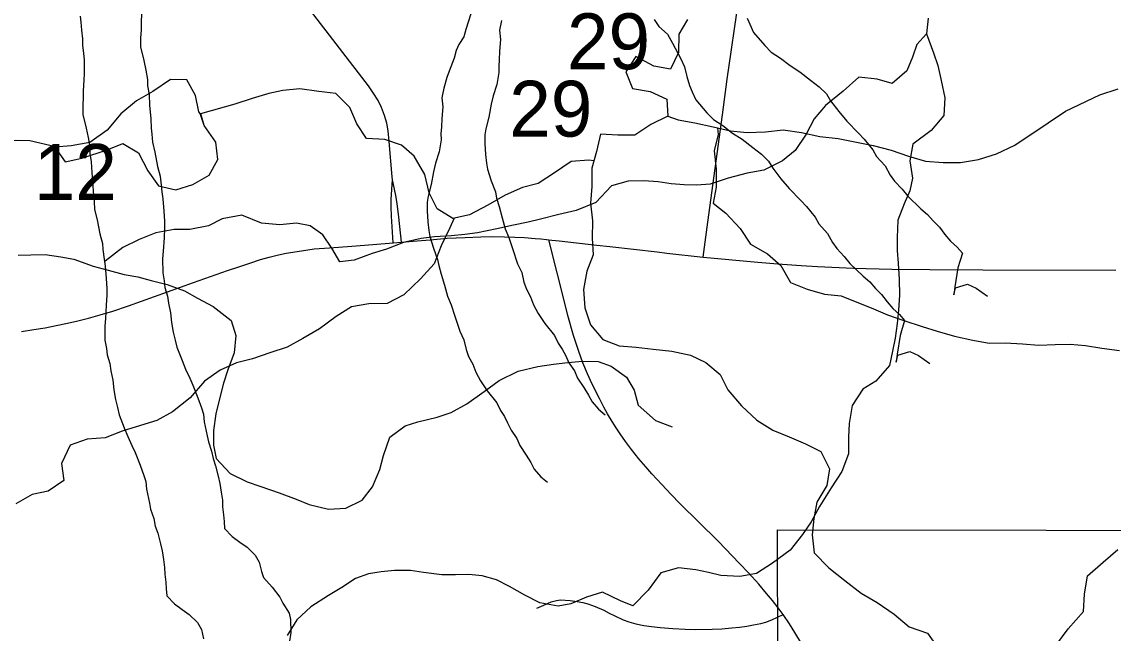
# Model space of a CAD drawing. Extents: x -21.1 to 50.3, y 0 to 22.1.
# Drawn here: x 3.891 to 4.709, y 20.075 to 20.533 of the extents above; entities that cross this region are included whole.
import ezdxf

# ---------------------------------------------------------------- set-up
doc = ezdxf.new("R2010")
doc.units = 0
for name, color, linetype in [('GM_X_Minor_Lake', 7, 'Continuous'), ('GM_X_Minor_River', 7, 'Continuous'), ('GM_X_Section', 7, 'Continuous'), ('GM_X_Section_Text', 7, 'Continuous'), ('GM_X_State_Route', 7, 'Continuous'), ('GM_X_Township_Road', 7, 'Continuous')]:
    doc.layers.add(name, color=color, linetype=linetype)

msp = doc.modelspace()

# ---------------------------------------------------------------- linework, layer by layer
at = {"layer": 'GM_X_Minor_Lake'}
for points in [[(4.02474, 20.46486), (4.02392, 20.46603), (4.02124, 20.4782), (4.01476, 20.48998), (4.00258, 20.49034), (3.98928, 20.4812), (3.97711, 20.47434), (3.96533, 20.46444), (3.95507, 20.45225), (3.94215, 20.44311), (3.92807, 20.44043), (3.9159, 20.43965), (3.92353, 20.42863)], [(3.92353, 20.42863), (3.93608, 20.43131), (3.95509, 20.43742), (3.96688, 20.44238), (3.97869, 20.43517), (3.98556, 20.42186), (3.99357, 20.41046), (4.00651, 20.40744), (4.01944, 20.41164), (4.0316, 20.4185), (4.03805, 20.4303), (4.03651, 20.44323), (4.02775, 20.45576), (4.02474, 20.46486)], [(3.92353, 20.42863), (3.93608, 20.43131), (3.95509, 20.43742), (3.96688, 20.44238), (3.97869, 20.43517), (3.98556, 20.42186), (3.99357, 20.41046), (4.00651, 20.40744), (4.01944, 20.41164), (4.0316, 20.4185), (4.03805, 20.4303), (4.03651, 20.44323), (4.02775, 20.45576), (4.0252, 20.4644)]]:
    msp.add_lwpolyline(points, dxfattribs=at)
at = {"layer": 'GM_X_Minor_River'}
for points in [[(3.93498, 20.53781), (3.93538, 20.53325)], [(3.98082, 20.54047), (3.98048, 20.53211), (3.98051, 20.52717), (3.98016, 20.52147), (3.9802, 20.51463), (3.98254, 20.50439), (3.98411, 20.49718), (3.98529, 20.49035), (3.98531, 20.48541), (3.98649, 20.47896), (3.98692, 20.47098), (3.98774, 20.46073), (3.98815, 20.45389), (3.98856, 20.44934), (3.98898, 20.44326), (3.99092, 20.43567), (3.99289, 20.42505), (3.99483, 20.41784), (3.99523, 20.41328), (3.99604, 20.40607), (3.99683, 20.40076), (3.99764, 20.39164), (3.99806, 20.38405), (3.99809, 20.37911), (3.99775, 20.37151), (3.99705, 20.36163), (3.9967, 20.35593), (3.99676, 20.34529), (3.99793, 20.33922), (3.99834, 20.33428), (4.00028, 20.32783), (4.00107, 20.32252), (4.00264, 20.31531), (4.00344, 20.3081), (4.00462, 20.30089), (4.00618, 20.29481), (4.00735, 20.2895), (4.01121, 20.27965), (4.01391, 20.27321), (4.017, 20.26638), (4.01931, 20.26108), (4.02317, 20.2516), (4.02587, 20.24402), (4.02742, 20.23947), (4.02784, 20.23377), (4.03018, 20.22315), (4.03097, 20.21859), (4.03329, 20.21177), (4.03446, 20.20608), (4.0364, 20.20077), (4.03834, 20.1928), (4.03952, 20.18749), (4.04069, 20.18104), (4.04149, 20.17496), (4.04152, 20.17003), (4.04231, 20.16395), (4.04272, 20.15902), (4.04313, 20.1537), (4.04887, 20.14765), (4.05461, 20.14351), (4.05996, 20.13974), (4.06608, 20.13369), (4.06916, 20.12839), (4.07072, 20.12156), (4.07226, 20.11701), (4.07878, 20.10983), (4.08453, 20.10226), (4.08684, 20.09772), (4.09145, 20.09015), (4.09262, 20.08559), (4.09267, 20.07572), (4.09157, 20.06773)], [(4.22769, 20.53944), (4.22395, 20.52764), (4.22246, 20.52231), (4.21868, 20.51659), (4.21681, 20.51202), (4.21531, 20.50632), (4.21156, 20.49642), (4.20968, 20.49185), (4.20745, 20.48386), (4.20596, 20.47663), (4.20677, 20.4698), (4.20605, 20.46106), (4.20571, 20.4546), (4.20535, 20.44966), (4.20538, 20.4451), (4.20391, 20.43597), (4.20129, 20.4276), (4.1998, 20.42113), (4.19795, 20.41162), (4.19572, 20.40287), (4.19498, 20.39831), (4.19502, 20.39185), (4.19545, 20.3835), (4.19624, 20.37704), (4.19703, 20.37249), (4.19974, 20.36377), (4.20284, 20.35543), (4.20363, 20.35087), (4.20556, 20.34442), (4.20789, 20.33608), (4.21023, 20.32773), (4.21292, 20.32129), (4.21564, 20.31295), (4.21951, 20.30157), (4.22259, 20.29513), (4.22415, 20.28792), (4.22608, 20.28261), (4.22916, 20.27693), (4.23148, 20.27087), (4.23494, 20.26443), (4.23993, 20.25686), (4.24722, 20.24778), (4.24991, 20.2421), (4.25298, 20.23756), (4.25529, 20.23301), (4.25799, 20.22733), (4.26221, 20.22127), (4.26452, 20.21597), (4.26913, 20.20877), (4.27259, 20.20309), (4.27528, 20.19817), (4.28026, 20.1925), (4.28523, 20.18835)], [(4.57054, 20.53612), (4.5694, 20.52437), (4.5747, 20.51034), (4.57773, 20.50085), (4.58038, 20.48948), (4.58302, 20.47658), (4.58225, 20.46331), (4.57277, 20.45193), (4.55912, 20.44169), (4.55684, 20.42917), (4.55873, 20.41628), (4.55683, 20.4068), (4.55265, 20.39694), (4.54772, 20.3848), (4.54733, 20.37191), (4.54733, 20.36204), (4.54808, 20.35256), (4.54883, 20.34043), (4.5492, 20.32867), (4.54844, 20.31729), (4.54729, 20.30743), (4.54577, 20.29643), (4.54387, 20.28657), (4.54159, 20.27595), (4.53135, 20.2642), (4.52149, 20.25813), (4.51352, 20.24599), (4.51124, 20.23234), (4.51086, 20.2221), (4.51085, 20.20958), (4.50591, 20.19631), (4.49794, 20.18417), (4.48922, 20.17014), (4.48277, 20.15876), (4.47632, 20.14928), (4.46722, 20.13752), (4.45394, 20.12766), (4.44181, 20.12007), (4.4293, 20.11779), (4.41527, 20.11855), (4.40579, 20.12083), (4.39632, 20.12272), (4.38343, 20.12424), (4.37016, 20.12044), (4.36068, 20.10755), (4.3493, 20.09579), (4.33982, 20.09958), (4.32656, 20.10603), (4.31443, 20.10223), (4.30267, 20.0973), (4.29319, 20.0954), (4.27955, 20.09806), (4.26818, 20.10374), (4.25681, 20.11019), (4.24696, 20.11512), (4.23634, 20.11815), (4.22611, 20.11929)], [(4.43496, 20.53616), (4.43689, 20.53161), (4.43959, 20.52555), (4.44802, 20.51572), (4.453, 20.5108), (4.45987, 20.50628), (4.46714, 20.50063), (4.47439, 20.49611), (4.48242, 20.4897), (4.48892, 20.48479), (4.49428, 20.4795), (4.49736, 20.4742), (4.50349, 20.46626), (4.50962, 20.45907), (4.51843, 20.45001), (4.52264, 20.44547), (4.52915, 20.43753), (4.53185, 20.4326), (4.53836, 20.42542), (4.5422, 20.41861), (4.54527, 20.41406), (4.55102, 20.40802), (4.55523, 20.40272), (4.56518, 20.39328), (4.57016, 20.38913), (4.57437, 20.38421), (4.57896, 20.37968), (4.58318, 20.37401), (4.5874, 20.36909), (4.59237, 20.36456), (4.5962, 20.36002), (4.59284, 20.34898), (4.59064, 20.33492), (4.58991, 20.32884), (4.59102, 20.33416), (4.60014, 20.33687), (4.60663, 20.33387), (4.61504, 20.32784)], [(3.93538, 20.53325), (3.9358, 20.52718), (3.9366, 20.52072), (3.93662, 20.51578), (3.93742, 20.51009), (3.93783, 20.50477), (3.93788, 20.49451), (3.93753, 20.48996), (3.93719, 20.48159), (3.93722, 20.47666), (3.93688, 20.47096), (3.93691, 20.46412), (3.93925, 20.45387), (3.94082, 20.44666), (3.942, 20.43983), (3.94202, 20.43489), (3.9432, 20.42844), (3.94363, 20.42047), (3.94445, 20.41021), (3.94487, 20.40338), (3.94527, 20.39882), (3.94569, 20.39275), (3.94763, 20.38516), (3.9496, 20.37453), (3.95154, 20.36732), (3.95195, 20.36277), (3.95275, 20.35556), (3.95354, 20.35024), (3.95435, 20.34113), (3.95477, 20.33353), (3.9548, 20.32859), (3.95446, 20.32099), (3.95376, 20.31111), (3.95341, 20.30541), (3.95347, 20.29477), (3.95464, 20.2887), (3.95505, 20.28377), (3.95699, 20.27732), (3.95778, 20.272), (3.95935, 20.26479), (3.96015, 20.25758), (3.96133, 20.25037), (3.96289, 20.2443), (3.96406, 20.23899), (3.96792, 20.22913), (3.97062, 20.22269), (3.97371, 20.21587), (3.97602, 20.21056), (3.97988, 20.20108), (3.98259, 20.1935), (3.98413, 20.18895), (3.98455, 20.18326), (3.98689, 20.17263), (3.98768, 20.16808), (3.99, 20.16125), (3.99117, 20.15556), (3.99311, 20.15025), (3.99505, 20.14229), (3.99623, 20.13697), (3.99741, 20.13052), (3.9982, 20.12445), (3.99823, 20.11951), (3.99902, 20.11343), (3.99943, 20.1085), (3.99984, 20.10318), (4.00559, 20.09714), (4.01132, 20.09299), (4.01667, 20.08922), (4.02279, 20.08318), (4.02587, 20.07787), (4.02743, 20.07105)], [(4.25074, 20.53437), (4.24925, 20.52715), (4.25005, 20.52031), (4.24934, 20.51157), (4.249, 20.50511), (4.24864, 20.50017), (4.24867, 20.49561), (4.2472, 20.48649), (4.24458, 20.47811), (4.24309, 20.47165), (4.24124, 20.46214), (4.23901, 20.45339), (4.23827, 20.44883), (4.23831, 20.44237), (4.23874, 20.43402), (4.23953, 20.42756), (4.24032, 20.42301), (4.24303, 20.41428), (4.24613, 20.40594), (4.24691, 20.40139), (4.24885, 20.39494), (4.25118, 20.38659), (4.25351, 20.37825), (4.25621, 20.37181), (4.25893, 20.36346), (4.26279, 20.35209), (4.26588, 20.34565), (4.26744, 20.33844), (4.26937, 20.33313), (4.27245, 20.32745), (4.27477, 20.32138), (4.27823, 20.31495), (4.28322, 20.30738), (4.29051, 20.2983), (4.2932, 20.29261), (4.29627, 20.28807), (4.29858, 20.28353), (4.30128, 20.27784), (4.3055, 20.27179), (4.30781, 20.26648), (4.31242, 20.25929), (4.31588, 20.25361), (4.31857, 20.24869), (4.32355, 20.24302), (4.32852, 20.23887)], [(4.39025, 20.53532), (4.38379, 20.52428), (4.38344, 20.51059), (4.37736, 20.49804), (4.36481, 20.5003), (4.35148, 20.50751), (4.34388, 20.49609), (4.34885, 20.48355), (4.36217, 20.48128), (4.37473, 20.47559), (4.37551, 20.46266), (4.36259, 20.45656), (4.3508, 20.44856), (4.33786, 20.44854), (4.32493, 20.44929), (4.3219, 20.43635), (4.31849, 20.4238), (4.31851, 20.41011), (4.31739, 20.39756), (4.31893, 20.38425), (4.31857, 20.37132), (4.31935, 20.35877), (4.3148, 20.34659), (4.31216, 20.33289), (4.31332, 20.3192), (4.31752, 20.30628), (4.32667, 20.29526), (4.33885, 20.29071), (4.35179, 20.28959), (4.36435, 20.28808), (4.37843, 20.28658), (4.39252, 20.28355), (4.40394, 20.27824), (4.41461, 20.26913), (4.42033, 20.25773), (4.43062, 20.24557), (4.44205, 20.23493), (4.45424, 20.22734), (4.46642, 20.22241), (4.47861, 20.2171), (4.49003, 20.21141), (4.49652, 20.19849), (4.49463, 20.18594), (4.48704, 20.17338), (4.48478, 20.1612), (4.48365, 20.14903), (4.48519, 20.13534), (4.49624, 20.12433), (4.50805, 20.11483), (4.52024, 20.10534), (4.53243, 20.09813), (4.545, 20.0894), (4.55643, 20.0799), (4.57013, 20.07536), (4.57738, 20.0651)], [(4.36513, 20.53526), (4.36859, 20.52996), (4.37509, 20.5243), (4.37893, 20.51748), (4.38509, 20.50574), (4.38779, 20.49968), (4.38973, 20.49247), (4.39167, 20.48564), (4.3936, 20.48109), (4.3963, 20.47503), (4.40473, 20.4652), (4.40971, 20.46029), (4.41658, 20.45577), (4.42385, 20.45011), (4.4311, 20.44559), (4.43913, 20.43918), (4.44563, 20.43428), (4.45099, 20.42899), (4.45407, 20.42369), (4.4602, 20.41574), (4.46633, 20.40856), (4.47514, 20.39949), (4.47935, 20.39495), (4.48587, 20.38701), (4.48856, 20.38209), (4.49507, 20.37491), (4.49892, 20.36809), (4.50199, 20.36355), (4.50773, 20.3575), (4.51195, 20.35221), (4.52189, 20.34276), (4.52687, 20.33861), (4.53108, 20.3337), (4.53567, 20.32917), (4.53989, 20.32349), (4.54411, 20.31857), (4.54908, 20.31404), (4.55292, 20.30951), (4.54955, 20.29847), (4.54735, 20.2844), (4.54662, 20.27832), (4.54773, 20.28365), (4.55685, 20.28635), (4.56334, 20.28335), (4.57175, 20.27732)], [(4.5694, 20.52437), (4.56219, 20.5164), (4.55878, 20.50692), (4.5546, 20.49668), (4.5436, 20.4872), (4.53223, 20.49061), (4.51859, 20.49213), (4.50683, 20.48151), (4.49355, 20.47089), (4.48521, 20.46065), (4.47914, 20.44927), (4.47079, 20.43713), (4.46131, 20.42917), (4.44728, 20.42234), (4.43477, 20.42006), (4.42074, 20.41627), (4.40709, 20.41172), (4.39724, 20.41096), (4.38776, 20.41133), (4.3779, 20.41209), (4.36805, 20.41361), (4.35743, 20.41437), (4.34568, 20.41398), (4.33317, 20.41057), (4.32141, 20.39805), (4.30662, 20.39198), (4.29373, 20.38895), (4.28008, 20.38553), (4.27061, 20.38326), (4.25961, 20.38098), (4.2471, 20.37832), (4.2327, 20.37529), (4.22322, 20.37415), (4.21298, 20.37301), (4.20047, 20.37225), (4.19061, 20.37111), (4.17735, 20.36808), (4.16445, 20.36315), (4.15384, 20.35973), (4.14019, 20.3548), (4.12958, 20.35366), (4.12351, 20.3639), (4.1167, 20.37376), (4.10722, 20.38059), (4.09699, 20.38248), (4.08448, 20.38134), (4.07083, 20.38248), (4.05605, 20.38854), (4.04127, 20.38589), (4.03103, 20.38058), (4.017, 20.37792), (4.00525, 20.37792), (3.9916, 20.37526), (3.97909, 20.37033), (3.96696, 20.36426), (3.95368, 20.35402)], [(4.31999, 20.4293), (4.3162, 20.42988), (4.30289, 20.42872), (4.29034, 20.42034), (4.27818, 20.41234), (4.26639, 20.40928), (4.25346, 20.40356), (4.24053, 20.39594), (4.22684, 20.3887), (4.21429, 20.38602), (4.20249, 20.39323), (4.19638, 20.40539), (4.19332, 20.41908), (4.18531, 20.43276), (4.17578, 20.44112), (4.16322, 20.44528), (4.14952, 20.44603), (4.14227, 20.45705), (4.13693, 20.46921), (4.12664, 20.47985), (4.1137, 20.48135), (4.09962, 20.48324), (4.08668, 20.48208), (4.07641, 20.47979), (4.06386, 20.47597), (4.05093, 20.47177), (4.02497, 20.46463)], [(4.37551, 20.46266), (4.38313, 20.46001), (4.39569, 20.45775), (4.40939, 20.45472), (4.42233, 20.45169), (4.43489, 20.45057), (4.44859, 20.45096), (4.4619, 20.4525), (4.4756, 20.45062), (4.48931, 20.44759), (4.50301, 20.44609), (4.51557, 20.44344), (4.52927, 20.4408), (4.54297, 20.43739), (4.55592, 20.43284), (4.56848, 20.42905), (4.5818, 20.42793), (4.59473, 20.42795), (4.60843, 20.43024), (4.62174, 20.43444), (4.63543, 20.44093), (4.66052, 20.45769), (4.67344, 20.46646), (4.6993, 20.47866), (4.71299, 20.48324)], [(4.41253, 20.45398), (4.4132, 20.44902), (4.41018, 20.43684), (4.41172, 20.42315), (4.41174, 20.40946), (4.40947, 20.39767), (4.419, 20.39007), (4.42967, 20.37868), (4.43729, 20.3669), (4.45024, 20.35969), (4.46015, 20.35095), (4.4674, 20.33803), (4.47996, 20.3331), (4.4929, 20.32932), (4.50546, 20.32819), (4.5184, 20.32288), (4.52792, 20.31909), (4.54011, 20.31378), (4.55229, 20.30961), (4.566, 20.30507), (4.57741, 20.30166), (4.59036, 20.29787), (4.60406, 20.29485), (4.61624, 20.29258), (4.62841, 20.29297), (4.64135, 20.29223), (4.65353, 20.2911), (4.66571, 20.2915), (4.67712, 20.29189), (4.68854, 20.29077), (4.70071, 20.28888), (4.71404, 20.287)], [(3.91631, 20.43976), (3.89725, 20.44419), (3.88774, 20.44456), (3.8748, 20.44417), (3.86224, 20.44491), (3.84854, 20.44375), (3.83637, 20.44222), (3.82686, 20.44068), (3.81355, 20.438), (3.80137, 20.43495), (3.78844, 20.43075), (3.77476, 20.4216), (3.76831, 20.40904), (3.75691, 20.39838), (3.74436, 20.39494), (3.73447, 20.39265), (3.72495, 20.39302)], [(4.21528, 20.38623), (4.21202, 20.37917), (4.20557, 20.36547), (4.20026, 20.35215), (4.19, 20.34073), (4.17747, 20.32892), (4.16492, 20.32244), (4.15122, 20.32205), (4.13829, 20.31975), (4.12688, 20.31251), (4.11434, 20.30336), (4.10179, 20.29612), (4.09001, 20.28964), (4.07708, 20.28544), (4.06415, 20.28086), (4.05197, 20.27781), (4.03981, 20.27247), (4.02802, 20.26408), (4.01739, 20.25152), (4.00409, 20.24124), (3.9923, 20.23475), (3.98013, 20.23094), (3.96643, 20.22674), (3.95351, 20.22178), (3.94019, 20.22062), (3.92726, 20.21604), (3.92081, 20.20234), (3.92273, 20.18979), (3.91095, 20.18179), (3.89878, 20.17911), (3.88661, 20.17225)], [(3.88842, 20.3585), (3.89792, 20.35874), (3.90856, 20.35896), (3.92031, 20.35726), (3.93016, 20.35559), (3.94451, 20.35043), (3.95586, 20.34722), (3.96796, 20.344), (3.97819, 20.34233), (3.98802, 20.33952), (4.00013, 20.33667), (4.01298, 20.33192), (4.02277, 20.32645), (4.03445, 20.3202), (4.04796, 20.30973), (4.05158, 20.29828), (4.05024, 20.28539), (4.04548, 20.27254), (4.04229, 20.26271), (4.03906, 20.24984), (4.03662, 20.23962), (4.03491, 20.22711), (4.03474, 20.2161), (4.03686, 20.20619), (4.04732, 20.19501), (4.06014, 20.18874), (4.07034, 20.18516), (4.08394, 20.1804), (4.09678, 20.17565), (4.1066, 20.1717), (4.12098, 20.16806), (4.1339, 20.169), (4.14615, 20.1749), (4.1539, 20.18504), (4.15942, 20.19787), (4.16224, 20.20846), (4.16701, 20.22207), (4.17854, 20.23063), (4.18808, 20.23353), (4.20256, 20.23711), (4.21288, 20.24075), (4.22475, 20.24703), (4.23781, 20.25633), (4.24895, 20.26451), (4.26311, 20.27152), (4.27798, 20.27509), (4.28978, 20.27681), (4.30044, 20.27817), (4.31146, 20.27914), (4.32324, 20.27897), (4.33306, 20.2754), (4.34433, 20.26725), (4.35025, 20.25728), (4.35312, 20.24622), (4.36623, 20.23462), (4.37869, 20.22987)], [(4.66641, 20.06597), (4.67553, 20.07853), (4.68692, 20.09148), (4.68767, 20.10441), (4.68993, 20.1181), (4.70171, 20.12839), (4.71273, 20.13791)], [(4.22611, 20.11929), (4.21625, 20.11891), (4.20602, 20.11891), (4.19237, 20.1208), (4.18252, 20.12232), (4.17039, 20.12232), (4.16053, 20.12118), (4.15105, 20.11966), (4.1412, 20.11625), (4.13096, 20.10942), (4.1211, 20.10335), (4.10783, 20.09501), (4.09721, 20.08514), (4.09, 20.07339)]]:
    msp.add_lwpolyline(points, dxfattribs=at)
at = {"layer": 'GM_X_Section'}
msp.add_lwpolyline([(4.45774, 20.15268), (5.46449, 20.1514), (5.46172, 19.1492), (4.46024, 19.14326)], close=True, dxfattribs=at)
at = {"layer": 'GM_X_State_Route'}
msp.add_line((4.16946, 20.3678), (4.1757, 20.36833), dxfattribs=at)
for points in [[(4.40197, 20.35714), (4.40541, 20.38338), (4.41642, 20.46371), (4.42, 20.49048), (4.42291, 20.51103), (4.42557, 20.52998), (4.43113, 20.56737)], [(4.19735, 20.37012), (4.21003, 20.3712), (4.22342, 20.37194), (4.23511, 20.37237), (4.24404, 20.37247), (4.25307, 20.37237), (4.26083, 20.37215), (4.26796, 20.37173), (4.27593, 20.37106), (4.28015, 20.37071), (4.28437, 20.37029), (4.28622, 20.37007)], [(3.89084, 20.3014), (3.90025, 20.3028), (3.90854, 20.30423), (3.91692, 20.30585), (3.92535, 20.30761), (3.9332, 20.30941), (3.94105, 20.31136), (3.94986, 20.31387), (3.9593, 20.31671), (3.97098, 20.32061), (4.01982, 20.33816), (4.04526, 20.34707), (4.05386, 20.34991), (4.06218, 20.35266), (4.06994, 20.35521), (4.07655, 20.35711), (4.08345, 20.3588), (4.08927, 20.36004), (4.10073, 20.36195), (4.11039, 20.36322), (4.12171, 20.36411), (4.1385, 20.36535), (4.15423, 20.36652), (4.16946, 20.3678)], [(4.1757, 20.36833), (4.1876, 20.36929), (4.19735, 20.37012)], [(4.28622, 20.37007), (4.28857, 20.36979), (4.29407, 20.3692), (4.32231, 20.36615), (4.33198, 20.36496), (4.36744, 20.36096), (4.37455, 20.36017), (4.40197, 20.35714)], [(4.4757, 20.06743), (4.4707, 20.07583), (4.46673, 20.08219), (4.46193, 20.0893), (4.45801, 20.09434), (4.45391, 20.09963), (4.44948, 20.10498), (4.44357, 20.1119), (4.43591, 20.12039), (4.42927, 20.12749), (4.41303, 20.1441), (4.38452, 20.17242), (4.37798, 20.17907), (4.37087, 20.18663), (4.36349, 20.19466), (4.35887, 20.19992), (4.35362, 20.20601), (4.34817, 20.21302), (4.34376, 20.21901), (4.33978, 20.22456), (4.33673, 20.22913), (4.3336, 20.23396), (4.33027, 20.23959), (4.32732, 20.24467), (4.3241, 20.25103), (4.31874, 20.26183), (4.31524, 20.26957), (4.31173, 20.27788), (4.30869, 20.28628), (4.30638, 20.2932), (4.30463, 20.29846), (4.30047, 20.31331), (4.29863, 20.32051), (4.28622, 20.37007)], [(4.40197, 20.35714), (4.44293, 20.35343), (4.45791, 20.3521), (4.47541, 20.35078), (4.4876, 20.34998), (4.51464, 20.34879), (4.54336, 20.34809), (4.57182, 20.34781), (4.61167, 20.34759), (4.71125, 20.34731)]]:
    msp.add_lwpolyline(points, dxfattribs=at)
at = {"layer": 'GM_X_Township_Road'}
for points in [[(4.16905, 20.41509), (4.16869, 20.41722), (4.16655, 20.44379), (4.16571, 20.45187), (4.16465, 20.4575), (4.16294, 20.46335), (4.16082, 20.4692), (4.15816, 20.47451), (4.15497, 20.47961), (4.15093, 20.48541), (4.10742, 20.54196)], [(4.16946, 20.3678), (4.16921, 20.37194), (4.16826, 20.38788), (4.16794, 20.3949), (4.16805, 20.40032), (4.16857, 20.40776), (4.16905, 20.41509)], [(4.1757, 20.36833), (4.17368, 20.38714), (4.17272, 20.39543), (4.17177, 20.40213), (4.17038, 20.40935), (4.16905, 20.41509)], [(4.27713, 20.09401), (4.28239, 20.09631), (4.28802, 20.09862), (4.2919, 20.09972), (4.29503, 20.10018), (4.30232, 20.09982), (4.30739, 20.09908), (4.31173, 20.09825), (4.31551, 20.09723), (4.32105, 20.09529), (4.32732, 20.09253), (4.33156, 20.09032), (4.33563, 20.08828), (4.34199, 20.08524), (4.34614, 20.08367), (4.35131, 20.08219), (4.35731, 20.081), (4.36305, 20.08023), (4.36958, 20.07943), (4.37908, 20.07869), (4.38849, 20.0782), (4.39615, 20.07804), (4.4087, 20.07823), (4.41589, 20.0786), (4.42337, 20.07915), (4.42918, 20.0798), (4.43463, 20.08054), (4.4397, 20.08136), (4.44514, 20.08256), (4.44892, 20.08358), (4.45326, 20.08515), (4.46193, 20.0893)]]:
    msp.add_lwpolyline(points, dxfattribs=at)

# ---------------------------------------------------------------- texts
at = {"layer": 'GM_X_Section_Text'}
for s, p in [('29', (4.29985, 20.49796)), ('29', (4.25656, 20.44744)), ('12', (3.90012, 20.40004))]:
    msp.add_text(s, height=0.041856, rotation=0.00001, dxfattribs=at).set_placement(p)

doc.saveas('drawing.dxf')
